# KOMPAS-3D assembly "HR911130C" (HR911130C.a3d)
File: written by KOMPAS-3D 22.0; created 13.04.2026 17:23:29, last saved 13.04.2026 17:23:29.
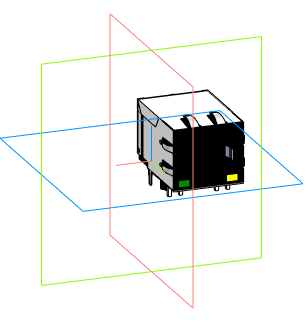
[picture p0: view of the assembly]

Document properties: Автор: Andrey; Полное имя файла: C:\Users\User1\Documents\HR911130C.a3d

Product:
- Component [detail]: HR911130C  | qty 1  | source file: HR911130C.m3d
- Part/product: HR911130C
    Комментарий: HR911130C

Referenced files in C:\Users\User1\Documents\: HR911130C.m3d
